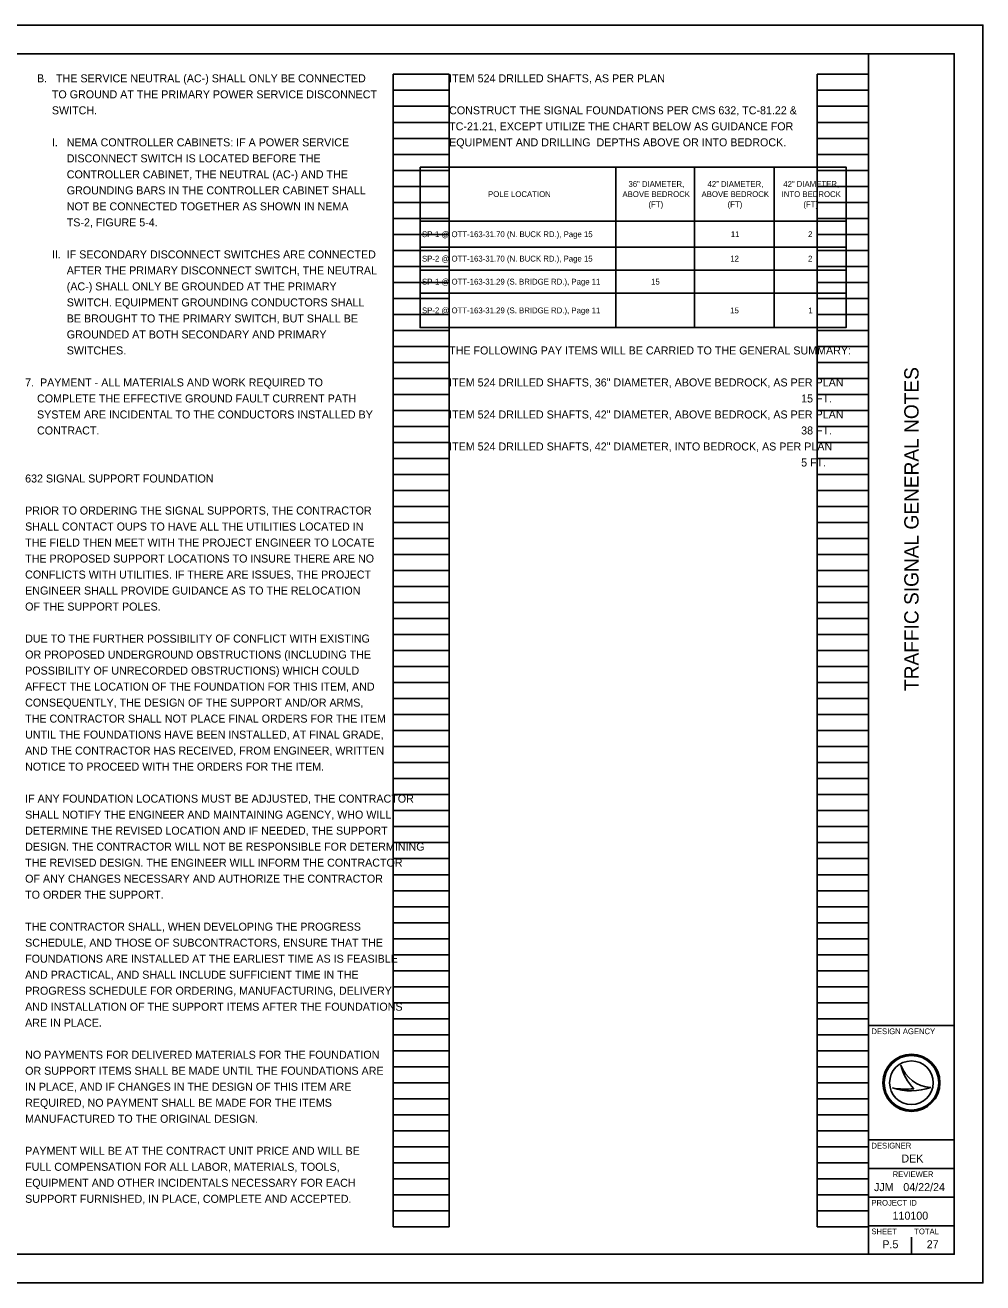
# Model space of a CAD drawing. Extents: x 0 to 44.9, y 0 to 22.
# Drawn here: x 17.24 to 34, y 0 to 22 of the extents above; entities that cross this region are included whole.
import ezdxf

# ---------------------------------------------------------------- set-up
doc = ezdxf.new("R2010")
doc.units = 0
for name, color, linetype in [('Default', 7, 'Continuous'), ('SH_Border', 7, 'Continuous'), ('SH_Cut_Line', 7, 'Continuous'), ('SH_Data', 7, 'Continuous'), ('SH_Text', 7, 'Continuous')]:
    doc.layers.add(name, color=color, linetype=linetype)

msp = doc.modelspace()

# ---------------------------------------------------------------- linework, layer by layer
at = {"layer": 'Default'}
for p, q in [((24.153, 19.518), (31.606, 19.518)), ((24.153, 19.518), (24.153, 16.71)), ((27.579, 19.518), (27.579, 16.71)), ((28.955, 19.518), (28.955, 16.71)), ((30.348, 19.518), (30.348, 16.71)), ((31.606, 19.518), (31.606, 16.71)), ((24.153, 18.569), (31.606, 18.569)), ((24.153, 18.118), (31.606, 18.118)), ((24.153, 17.714), (31.606, 17.714)), ((24.153, 17.311), (31.606, 17.311)), ((24.153, 16.71), (31.606, 16.71))]:
    msp.add_line(p, q, dxfattribs=at)
for points in [[(24.153, 19.518), (27.579, 19.518), (27.579, 18.569), (24.153, 18.569)], [(27.579, 19.518), (28.955, 19.518), (28.955, 18.569), (27.579, 18.569)], [(28.955, 19.518), (30.348, 19.518), (30.348, 18.569), (28.955, 18.569)], [(30.348, 19.518), (31.606, 19.518), (31.606, 18.569), (30.348, 18.569)], [(24.153, 18.569), (27.579, 18.569), (27.579, 18.118), (24.153, 18.118)], [(27.579, 18.569), (28.955, 18.569), (28.955, 18.118), (27.579, 18.118)], [(28.955, 18.569), (30.348, 18.569), (30.348, 18.118), (28.955, 18.118)], [(30.348, 18.569), (31.606, 18.569), (31.606, 18.118), (30.348, 18.118)], [(24.153, 18.118), (27.579, 18.118), (27.579, 17.714), (24.153, 17.714)], [(27.579, 18.118), (28.955, 18.118), (28.955, 17.714), (27.579, 17.714)], [(28.955, 18.118), (30.348, 18.118), (30.348, 17.714), (28.955, 17.714)], [(30.348, 18.118), (31.606, 18.118), (31.606, 17.714), (30.348, 17.714)], [(24.153, 17.714), (27.579, 17.714), (27.579, 17.311), (24.153, 17.311)], [(27.579, 17.714), (28.955, 17.714), (28.955, 17.311), (27.579, 17.311)], [(28.955, 17.714), (30.348, 17.714), (30.348, 17.311), (28.955, 17.311)], [(30.348, 17.714), (31.606, 17.714), (31.606, 17.311), (30.348, 17.311)], [(24.153, 17.311), (27.579, 17.311), (27.579, 16.71), (24.153, 16.71)], [(27.579, 17.311), (28.955, 17.311), (28.955, 16.71), (27.579, 16.71)], [(28.955, 17.311), (30.348, 17.311), (30.348, 16.71), (28.955, 16.71)], [(30.348, 17.311), (31.606, 17.311), (31.606, 16.71), (30.348, 16.71)]]:
    msp.add_lwpolyline(points, close=True, dxfattribs=at)
at = {"layer": 'SH_Border'}
for p, q in [((32, 0.5), (32, 21.5)), ((32, 4.5), (33.5, 4.5)), ((32, 2.5), (33.5, 2.5)), ((32, 2), (33.5, 2)), ((32, 1.5), (33.5, 1.5)), ((32, 1), (33.5, 1))]:
    msp.add_line(p, q, dxfattribs=at)
msp.add_lwpolyline([(1.5, 21.5), (33.5, 21.5), (33.5, 0.5), (1.5, 0.5)], close=True, dxfattribs=at)
at = {"layer": 'SH_Cut_Line'}
msp.add_lwpolyline([(0, 0), (34, 0), (34, 22), (0, 22)], close=True, dxfattribs=at)
at = {"layer": 'SH_Data'}
for p, q in [((23.68, 0.98), (23.68, 21.14)), ((23.68, 21.14), (24.66, 21.14)), ((24.66, 0.98), (24.66, 21.14)), ((31.1, 0.98), (31.1, 21.14)), ((31.1, 21.14), (32, 21.14)), ((32, 0.98), (32, 21.14)), ((23.68, 20.86), (24.66, 20.86)), ((31.1, 20.86), (32, 20.86)), ((23.68, 20.58), (24.66, 20.58)), ((31.1, 20.58), (32, 20.58)), ((23.68, 20.3), (24.66, 20.3)), ((31.1, 20.3), (32, 20.3)), ((23.68, 20.02), (24.66, 20.02)), ((31.1, 20.02), (32, 20.02)), ((23.68, 19.74), (24.66, 19.74)), ((31.1, 19.74), (32, 19.74)), ((23.68, 19.46), (24.66, 19.46)), ((31.1, 19.46), (32, 19.46)), ((23.68, 19.18), (24.66, 19.18)), ((31.1, 19.18), (32, 19.18)), ((23.68, 18.9), (24.66, 18.9)), ((31.1, 18.9), (32, 18.9)), ((23.68, 18.62), (24.66, 18.62)), ((31.1, 18.62), (32, 18.62)), ((23.68, 18.34), (24.66, 18.34)), ((31.1, 18.34), (32, 18.34)), ((23.68, 18.06), (24.66, 18.06)), ((31.1, 18.06), (32, 18.06)), ((23.68, 17.78), (24.66, 17.78)), ((31.1, 17.78), (32, 17.78)), ((23.68, 17.5), (24.66, 17.5)), ((31.1, 17.5), (32, 17.5)), ((23.68, 17.22), (24.66, 17.22)), ((31.1, 17.22), (32, 17.22)), ((23.68, 16.94), (24.66, 16.94)), ((31.1, 16.94), (32, 16.94)), ((23.68, 16.66), (24.66, 16.66)), ((31.1, 16.66), (32, 16.66)), ((23.68, 16.38), (24.66, 16.38)), ((31.1, 16.38), (32, 16.38)), ((23.68, 16.1), (24.66, 16.1)), ((31.1, 16.1), (32, 16.1)), ((23.68, 15.82), (24.66, 15.82)), ((31.1, 15.82), (32, 15.82)), ((23.68, 15.54), (24.66, 15.54)), ((31.1, 15.54), (32, 15.54)), ((23.68, 15.26), (24.66, 15.26)), ((31.1, 15.26), (32, 15.26)), ((23.68, 14.98), (24.66, 14.98)), ((31.1, 14.98), (32, 14.98)), ((23.68, 14.7), (24.66, 14.7)), ((31.1, 14.7), (32, 14.7)), ((23.68, 14.42), (24.66, 14.42)), ((31.1, 14.42), (32, 14.42)), ((23.68, 14.14), (24.66, 14.14)), ((31.1, 14.14), (32, 14.14)), ((23.68, 13.86), (24.66, 13.86)), ((31.1, 13.86), (32, 13.86)), ((23.68, 13.58), (24.66, 13.58)), ((31.1, 13.58), (32, 13.58)), ((23.68, 13.3), (24.66, 13.3)), ((31.1, 13.3), (32, 13.3)), ((23.68, 13.02), (24.66, 13.02)), ((31.1, 13.02), (32, 13.02)), ((23.68, 12.74), (24.66, 12.74)), ((31.1, 12.74), (32, 12.74)), ((23.68, 12.46), (24.66, 12.46)), ((31.1, 12.46), (32, 12.46)), ((23.68, 12.18), (24.66, 12.18)), ((31.1, 12.18), (32, 12.18)), ((23.68, 11.9), (24.66, 11.9)), ((31.1, 11.9), (32, 11.9)), ((23.68, 11.62), (24.66, 11.62)), ((31.1, 11.62), (32, 11.62)), ((23.68, 11.34), (24.66, 11.34)), ((31.1, 11.34), (32, 11.34)), ((23.68, 11.06), (24.66, 11.06)), ((31.1, 11.06), (32, 11.06)), ((23.68, 10.78), (24.66, 10.78)), ((31.1, 10.78), (32, 10.78)), ((23.68, 10.5), (24.66, 10.5)), ((31.1, 10.5), (32, 10.5)), ((23.68, 10.22), (24.66, 10.22)), ((31.1, 10.22), (32, 10.22)), ((23.68, 9.94), (24.66, 9.94)), ((31.1, 9.94), (32, 9.94)), ((23.68, 9.66), (24.66, 9.66)), ((31.1, 9.66), (32, 9.66)), ((23.68, 9.38), (24.66, 9.38)), ((31.1, 9.38), (32, 9.38)), ((23.68, 9.1), (24.66, 9.1)), ((31.1, 9.1), (32, 9.1)), ((23.68, 8.82), (24.66, 8.82)), ((31.1, 8.82), (32, 8.82)), ((23.68, 8.54), (24.66, 8.54)), ((31.1, 8.54), (32, 8.54)), ((23.68, 8.26), (24.66, 8.26)), ((31.1, 8.26), (32, 8.26)), ((23.68, 7.98), (24.66, 7.98)), ((31.1, 7.98), (32, 7.98)), ((23.68, 7.7), (24.66, 7.7)), ((31.1, 7.7), (32, 7.7)), ((23.68, 7.42), (24.66, 7.42)), ((31.1, 7.42), (32, 7.42)), ((23.68, 7.14), (24.66, 7.14)), ((31.1, 7.14), (32, 7.14)), ((23.68, 6.86), (24.66, 6.86)), ((31.1, 6.86), (32, 6.86)), ((23.68, 6.58), (24.66, 6.58)), ((31.1, 6.58), (32, 6.58)), ((23.68, 6.3), (24.66, 6.3)), ((31.1, 6.3), (32, 6.3)), ((23.68, 6.02), (24.66, 6.02)), ((31.1, 6.02), (32, 6.02)), ((23.68, 5.74), (24.66, 5.74)), ((31.1, 5.74), (32, 5.74)), ((23.68, 5.46), (24.66, 5.46)), ((31.1, 5.46), (32, 5.46)), ((23.68, 5.18), (24.66, 5.18)), ((31.1, 5.18), (32, 5.18)), ((23.68, 4.9), (24.66, 4.9)), ((31.1, 4.9), (32, 4.9)), ((23.68, 4.62), (24.66, 4.62)), ((31.1, 4.62), (32, 4.62)), ((23.68, 4.34), (24.66, 4.34)), ((31.1, 4.34), (32, 4.34)), ((23.68, 4.06), (24.66, 4.06)), ((31.1, 4.06), (32, 4.06)), ((23.68, 3.78), (24.66, 3.78)), ((31.1, 3.78), (32, 3.78)), ((32.567, 3.81), (32.567, 3.81)), ((23.68, 3.5), (24.66, 3.5)), ((31.1, 3.5), (32, 3.5)), ((32.417, 3.41), (32.417, 3.41)), ((32.75, 3.5), (32.75, 3.5)), ((33.087, 3.419), (33.087, 3.419)), ((23.68, 3.22), (24.66, 3.22)), ((31.1, 3.22), (32, 3.22)), ((23.68, 2.94), (24.66, 2.94)), ((31.1, 2.94), (32, 2.94)), ((23.68, 2.66), (24.66, 2.66)), ((31.1, 2.66), (32, 2.66)), ((23.68, 2.38), (24.66, 2.38)), ((31.1, 2.38), (32, 2.38)), ((23.68, 2.1), (24.66, 2.1)), ((31.1, 2.1), (32, 2.1)), ((23.68, 1.82), (24.66, 1.82)), ((31.1, 1.82), (32, 1.82)), ((23.68, 1.54), (24.66, 1.54)), ((31.1, 1.54), (32, 1.54)), ((23.68, 1.26), (24.66, 1.26)), ((31.1, 1.26), (32, 1.26)), ((23.68, 0.98), (24.66, 0.98)), ((31.1, 0.98), (32, 0.98)), ((32.375, 0.675), (32.375, 0.675)), ((32.75, 0.5), (32.75, 0.8))]:
    msp.add_line(p, q, dxfattribs=at)
for radius in [0.5, 0.477, 0.477, 0.382]:
    msp.add_circle((32.75, 3.5), radius, dxfattribs=at)
for centre, radius, start, end in [((33.116, 3.998), 0.58, 198.9257, 198.9319), ((33.347, 3.97), 0.796, 191.6379, 191.6421), ((33.116, 3.998), 0.58, 198.9319, 267.1657), ((33.347, 3.97), 0.796, 191.6421, 226.0947), ((32.739, 4.37), 1.013, 251.4576, 290.0832), ((32.648, 4.654), 1.266, 259.4964, 259.4995), ((32.739, 4.37), 1.013, 251.4527, 251.4576), ((32.648, 4.654), 1.266, 259.4995, 276.6672)]:
    msp.add_arc(centre, radius, start, end, dxfattribs=at)

# ---------------------------------------------------------------- texts
at = {"layer": 'Default'}
for s, height, p in [('36” DIAMETER, ', 0.1019, (27.798, 19.171)), ('42” DIAMETER, ', 0.1019, (29.182, 19.171)), ('42” DIAMETER, ', 0.1019, (30.508, 19.171)), ('POLE LOCATION', 0.1019, (25.341, 18.993)), ('ABOVE BEDROCK ', 0.1019, (27.693, 18.993)), ('(FT)', 0.1019, (28.149, 18.814)), ('ABOVE BEDROCK ', 0.1019, (29.077, 18.993)), ('(FT)', 0.1019, (29.533, 18.814)), ('INTO BEDROCK ', 0.1019, (30.478, 18.993)), ('(FT)', 0.1019, (30.859, 18.814)), ('SP-1 @ OTT-163-31.70 (N. BUCK RD.), Page 15', 0.1019, (24.185, 18.292)), ('11', 0.1019, (29.59, 18.292)), ('2', 0.102, (30.941, 18.292)), ('SP-2 @ OTT-163-31.70 (N. BUCK RD.), Page 15', 0.1019, (24.185, 17.865)), ('12', 0.1019, (29.58, 17.865)), ('2', 0.102, (30.941, 17.865)), ('SP-1 @ OTT-163-31.29 (S. BRIDGE RD.), Page 11', 0.1019, (24.185, 17.462)), ('15', 0.1019, (28.195, 17.462)), ('SP-2 @ OTT-163-31.29 (S. BRIDGE RD.), Page 11', 0.1019, (24.185, 16.959)), ('15', 0.1019, (29.579, 16.959)), ('1', 0.102, (30.946, 16.959))]:
    msp.add_text(s, height=height, dxfattribs=at).set_placement(p)
at = {"layer": 'SH_Data'}
msp.add_text('TRAFFIC SIGNAL GENERAL NOTES', height=0.25, rotation=90, dxfattribs=at).set_placement((32.875, 10.353))
for s, height, p in [('DESIGN AGENCY', 0.1, (32.05, 4.35)), ('DESIGNER', 0.1, (32.05, 2.35)), ('DEK', 0.14, (32.574, 2.105)), ('REVIEWER', 0.1, (32.422, 1.85)), ('JJM', 0.14, (32.095, 1.605)), ('04/22/24', 0.14, (32.608, 1.605)), ('PROJECT ID', 0.1, (32.05, 1.35)), ('110100', 0.14, (32.419, 1.105)), ('SHEET', 0.1, (32.05, 0.85)), ('TOTAL', 0.1, (32.8, 0.85)), ('P.5', 0.14, (32.241, 0.605)), ('27', 0.14, (33.018, 0.605))]:
    msp.add_text(s, height=height, dxfattribs=at).set_placement(p)
at = {"layer": 'SH_Text'}
for s, p in [('    B.   THE SERVICE NEUTRAL (AC-) SHALL ONLY BE CONNECTED', (17.24, 21)), ('ITEM 524 DRILLED SHAFTS, AS PER PLAN', (24.66, 21)), ('         TO GROUND AT THE PRIMARY POWER SERVICE DISCONNECT', (17.24, 20.72)), ('         SWITCH.', (17.24, 20.44)), ('CONSTRUCT THE SIGNAL FOUNDATIONS PER CMS 632, TC-81.22 &', (24.66, 20.44)), ('TC-21.21, EXCEPT UTILIZE THE CHART BELOW AS GUIDANCE FOR ', (24.66, 20.16)), ('         I.   NEMA CONTROLLER CABINETS: IF A POWER SERVICE', (17.24, 19.88)), ('EQUIPMENT AND DRILLING  DEPTHS ABOVE OR INTO BEDROCK.', (24.66, 19.88)), ('              DISCONNECT SWITCH IS LOCATED BEFORE THE', (17.24, 19.6)), ('              CONTROLLER CABINET, THE NEUTRAL (AC-) AND THE', (17.24, 19.32)), ('              GROUNDING BARS IN THE CONTROLLER CABINET SHALL', (17.24, 19.04)), ('              NOT BE CONNECTED TOGETHER AS SHOWN IN NEMA', (17.24, 18.76)), ('              TS-2, FIGURE 5-4.', (17.24, 18.48)), ('         II.  IF SECONDARY DISCONNECT SWITCHES ARE CONNECTED', (17.24, 17.92)), ('              AFTER THE PRIMARY DISCONNECT SWITCH, THE NEUTRAL', (17.24, 17.64)), ('              (AC-) SHALL ONLY BE GROUNDED AT THE PRIMARY', (17.24, 17.36)), ('              SWITCH. EQUIPMENT GROUNDING CONDUCTORS SHALL', (17.24, 17.08)), ('              BE BROUGHT TO THE PRIMARY SWITCH, BUT SHALL BE', (17.24, 16.8)), ('              GROUNDED AT BOTH SECONDARY AND PRIMARY', (17.24, 16.52)), ('              SWITCHES.', (17.24, 16.24)), ('THE FOLLOWING PAY ITEMS WILL BE CARRIED TO THE GENERAL SUMMARY:', (24.66, 16.24)), ('7.  PAYMENT - ALL MATERIALS AND WORK REQUIRED TO', (17.24, 15.68)), ('ITEM 524 DRILLED SHAFTS, 36" DIAMETER, ABOVE BEDROCK, AS PER PLAN', (24.66, 15.68)), ('    COMPLETE THE EFFECTIVE GROUND FAULT CURRENT PATH', (17.24, 15.4)), ('15 FT.', (30.82, 15.4)), ('    SYSTEM ARE INCIDENTAL TO THE CONDUCTORS INSTALLED BY', (17.24, 15.12)), ('ITEM 524 DRILLED SHAFTS, 42" DIAMETER, ABOVE BEDROCK, AS PER PLAN', (24.66, 15.12)), ('    CONTRACT.', (17.24, 14.84)), ('38 FT.', (30.82, 14.84)), ('ITEM 524 DRILLED SHAFTS, 42" DIAMETER, INTO BEDROCK, AS PER PLAN ', (24.66, 14.56)), ('5 FT.', (30.82, 14.28)), ('632 SIGNAL SUPPORT FOUNDATION', (17.24, 14)), ('PRIOR TO ORDERING THE SIGNAL SUPPORTS, THE CONTRACTOR', (17.24, 13.44)), ('SHALL CONTACT OUPS TO HAVE ALL THE UTILITIES LOCATED IN', (17.24, 13.16)), ('THE FIELD THEN MEET WITH THE PROJECT ENGINEER TO LOCATE', (17.24, 12.88)), ('THE PROPOSED SUPPORT LOCATIONS TO INSURE THERE ARE NO', (17.24, 12.6)), ('CONFLICTS WITH UTILITIES. IF THERE ARE ISSUES, THE PROJECT', (17.24, 12.32)), ('ENGINEER SHALL PROVIDE GUIDANCE AS TO THE RELOCATION', (17.24, 12.04)), ('OF THE SUPPORT POLES.', (17.24, 11.76)), ('DUE TO THE FURTHER POSSIBILITY OF CONFLICT WITH EXISTING', (17.24, 11.2)), ('OR PROPOSED UNDERGROUND OBSTRUCTIONS (INCLUDING THE', (17.24, 10.92)), ('POSSIBILITY OF UNRECORDED OBSTRUCTIONS) WHICH COULD', (17.24, 10.64)), ('AFFECT THE LOCATION OF THE FOUNDATION FOR THIS ITEM, AND', (17.24, 10.36)), ('CONSEQUENTLY, THE DESIGN OF THE SUPPORT AND/OR ARMS, ', (17.24, 10.08)), ('THE CONTRACTOR SHALL NOT PLACE FINAL ORDERS FOR THE ITEM', (17.24, 9.8)), ('UNTIL THE FOUNDATIONS HAVE BEEN INSTALLED, AT FINAL GRADE,', (17.24, 9.52)), ('AND THE CONTRACTOR HAS RECEIVED, FROM ENGINEER, WRITTEN', (17.24, 9.24)), ('NOTICE TO PROCEED WITH THE ORDERS FOR THE ITEM.', (17.24, 8.96)), ('IF ANY FOUNDATION LOCATIONS MUST BE ADJUSTED, THE CONTRACTOR', (17.24, 8.4)), ('SHALL NOTIFY THE ENGINEER AND MAINTAINING AGENCY, WHO WILL', (17.24, 8.12)), ('DETERMINE THE REVISED LOCATION AND IF NEEDED, THE SUPPORT', (17.24, 7.84)), ('DESIGN. THE CONTRACTOR WILL NOT BE RESPONSIBLE FOR DETERMINING', (17.24, 7.56)), ('THE REVISED DESIGN. THE ENGINEER WILL INFORM THE CONTRACTOR', (17.24, 7.28)), ('OF ANY CHANGES NECESSARY AND AUTHORIZE THE CONTRACTOR', (17.24, 7)), ('TO ORDER THE SUPPORT.', (17.24, 6.72)), ('THE CONTRACTOR SHALL, WHEN DEVELOPING THE PROGRESS', (17.24, 6.16)), ('SCHEDULE, AND THOSE OF SUBCONTRACTORS, ENSURE THAT THE', (17.24, 5.88)), ('FOUNDATIONS ARE INSTALLED AT THE EARLIEST TIME AS IS FEASIBLE', (17.24, 5.6)), ('AND PRACTICAL, AND SHALL INCLUDE SUFFICIENT TIME IN THE', (17.24, 5.32)), ('PROGRESS SCHEDULE FOR ORDERING, MANUFACTURING, DELIVERY,', (17.24, 5.04)), ('AND INSTALLATION OF THE SUPPORT ITEMS AFTER THE FOUNDATIONS', (17.24, 4.76)), ('ARE IN PLACE.', (17.24, 4.48)), ('NO PAYMENTS FOR DELIVERED MATERIALS FOR THE FOUNDATION', (17.24, 3.92)), ('OR SUPPORT ITEMS SHALL BE MADE UNTIL THE FOUNDATIONS ARE', (17.24, 3.64)), ('IN PLACE, AND IF CHANGES IN THE DESIGN OF THIS ITEM ARE', (17.24, 3.36)), ('REQUIRED, NO PAYMENT SHALL BE MADE FOR THE ITEMS ', (17.24, 3.08)), ('MANUFACTURED TO THE ORIGINAL DESIGN.', (17.24, 2.8)), ('PAYMENT WILL BE AT THE CONTRACT UNIT PRICE AND WILL BE', (17.24, 2.24)), ('FULL COMPENSATION FOR ALL LABOR, MATERIALS, TOOLS,', (17.24, 1.96)), ('EQUIPMENT AND OTHER INCIDENTALS NECESSARY FOR EACH', (17.24, 1.68)), ('SUPPORT FURNISHED, IN PLACE, COMPLETE AND ACCEPTED.', (17.24, 1.4))]:
    msp.add_text(s, height=0.14, dxfattribs=at).set_placement(p)

doc.saveas('drawing.dxf')
